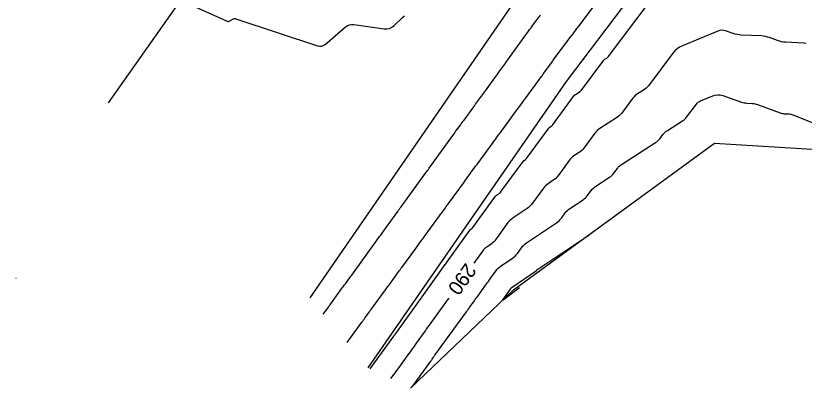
# Model space of a CAD drawing. Extents: x 1574966 to 1597594, y 720505 to 737840.
# Drawn here: x 1577544.3 to 1577874.4, y 724072.7 to 724228.5 of the extents above; entities that cross this region are included whole.
import ezdxf

# ---------------------------------------------------------------- set-up
doc = ezdxf.new("R2010")
doc.units = 0
for name, color, linetype in [('R_Contour Annot', 7, 'Continuous'), ('R_Contours', 7, 'Continuous'), ('S_BREAKLINE', 7, 'Continuous'), ('S_GRD_PT_SYM', 7, 'Continuous')]:
    doc.layers.add(name, color=color, linetype=linetype)

msp = doc.modelspace()

# ---------------------------------------------------------------- linework, layer by layer
at = {"layer": 'R_Contours'}
for points in [[(1577615.4, 724234.05), (1577632.74, 724226.3), (1577633.06, 724226.19), (1577633.37, 724226.17), (1577633.68, 724226.24), (1577633.98, 724226.39), (1577635.18, 724227.15), (1577635.49, 724227.3), (1577635.8, 724227.38), (1577636.13, 724227.38), (1577636.46, 724227.3), (1577670.63, 724215.95), (1577671.48, 724215.77), (1577672.28, 724215.81), (1577673.04, 724216.07), (1577673.76, 724216.56), (1577682.38, 724223.9), (1577683.15, 724224.43), (1577683.98, 724224.78), (1577684.86, 724224.93), (1577685.8, 724224.89), (1577698.58, 724223.1), (1577699.73, 724223.06), (1577700.8, 724223.28), (1577701.79, 724223.74), (1577702.69, 724224.46), (1577706.19, 724227.88), (1577707.07, 724228.59)], [(1577682.97, 724091.79), (1577689.18, 724100.24), (1577689.53, 724100.73), (1577689.89, 724101.22), (1577690.24, 724101.7), (1577690.59, 724102.19), (1577692, 724104.14), (1577692.35, 724104.63), (1577692.71, 724105.12), (1577693.06, 724105.61), (1577693.42, 724106.09), (1577699.09, 724113.81), (1577699.43, 724114.28), (1577699.78, 724114.75), (1577700.12, 724115.22), (1577700.46, 724115.7), (1577704.52, 724121.33), (1577704.86, 724121.79), (1577705.2, 724122.26), (1577705.54, 724122.72), (1577705.88, 724123.19), (1577711.72, 724131.14), (1577712.05, 724131.59), (1577712.38, 724132.04), (1577712.7, 724132.49), (1577713.03, 724132.94), (1577714.33, 724134.74), (1577714.66, 724135.19), (1577714.98, 724135.64), (1577715.31, 724136.09), (1577715.64, 724136.53), (1577721.68, 724144.75), (1577722, 724145.19), (1577722.31, 724145.62), (1577722.63, 724146.05), (1577722.94, 724146.49), (1577724.2, 724148.23), (1577724.51, 724148.67), (1577724.83, 724149.1), (1577725.15, 724149.53), (1577725.46, 724149.97), (1577731.71, 724158.46), (1577732.01, 724158.87), (1577732.32, 724159.29), (1577732.62, 724159.71), (1577732.92, 724160.13), (1577736.53, 724165.13), (1577736.83, 724165.54), (1577737.13, 724165.95), (1577737.43, 724166.36), (1577737.73, 724166.77), (1577744.14, 724175.49), (1577744.43, 724175.89), (1577744.72, 724176.28), (1577745.01, 724176.68), (1577745.3, 724177.08), (1577746.45, 724178.67), (1577746.73, 724179.06), (1577747.02, 724179.46), (1577747.31, 724179.86), (1577747.6, 724180.25), (1577754.22, 724189.25), (1577754.5, 724189.63), (1577754.77, 724190.01), (1577755.05, 724190.39), (1577755.33, 724190.77), (1577756.43, 724192.29), (1577756.7, 724192.68), (1577756.98, 724193.06), (1577757.26, 724193.44), (1577757.54, 724193.82), (1577764.36, 724203.09), (1577764.63, 724203.45), (1577764.89, 724203.82), (1577765.16, 724204.18), (1577765.42, 724204.55), (1577768.56, 724208.9), (1577768.83, 724209.26), (1577769.09, 724209.61), (1577769.35, 724209.97), (1577769.62, 724210.32), (1577776.86, 724219.95), (1577777.13, 724220.3), (1577777.39, 724220.66), (1577777.65, 724221.01), (1577777.91, 724221.37), (1577778.95, 724222.8), (1577779.21, 724223.16), (1577779.47, 724223.52), (1577779.73, 724223.87), (1577779.99, 724224.23), (1577787.26, 724233.88)], [(1577692.73, 724080.76), (1577702.55, 724094.42), (1577702.62, 724094.52), (1577702.69, 724094.62), (1577702.76, 724094.72), (1577702.83, 724094.81), (1577703.12, 724095.21), (1577703.19, 724095.3), (1577703.26, 724095.4), (1577703.33, 724095.5), (1577703.4, 724095.6), (1577712.98, 724108.93), (1577713.06, 724109.04), (1577713.13, 724109.14), (1577713.21, 724109.25), (1577713.29, 724109.36), (1577714.14, 724110.53), (1577714.2, 724110.62), (1577714.26, 724110.7), (1577714.33, 724110.79), (1577714.39, 724110.88), (1577724.11, 724124.4), (1577724.17, 724124.49), (1577724.24, 724124.59), (1577724.31, 724124.68), (1577724.38, 724124.78), (1577724.66, 724125.16), (1577724.73, 724125.26), (1577724.8, 724125.35), (1577724.87, 724125.45), (1577724.93, 724125.55), (1577734.58, 724138.96), (1577734.65, 724139.05), (1577734.73, 724139.14), (1577734.82, 724139.22), (1577734.91, 724139.28), (1577735.3, 724139.55), (1577735.39, 724139.62), (1577735.48, 724139.69), (1577735.55, 724139.78), (1577735.63, 724139.87), (1577745.15, 724153.04), (1577745.23, 724153.15), (1577745.32, 724153.24), (1577745.42, 724153.33), (1577745.52, 724153.41), (1577746.87, 724154.31), (1577746.98, 724154.39), (1577747.08, 724154.48), (1577747.18, 724154.57), (1577747.26, 724154.68), (1577756.71, 724167.62), (1577756.81, 724167.74), (1577756.91, 724167.85), (1577757.02, 724167.95), (1577757.15, 724168.04), (1577757.66, 724168.38), (1577757.78, 724168.47), (1577757.9, 724168.56), (1577758, 724168.67), (1577758.1, 724168.79), (1577767.4, 724181.46), (1577767.5, 724181.59), (1577767.62, 724181.71), (1577767.75, 724181.82), (1577767.89, 724181.92), (1577768.46, 724182.29), (1577768.59, 724182.39), (1577768.72, 724182.5), (1577768.84, 724182.62), (1577768.95, 724182.75), (1577778.09, 724195.14), (1577778.21, 724195.29), (1577778.34, 724195.42), (1577778.48, 724195.54), (1577778.63, 724195.64), (1577780.55, 724196.87), (1577780.7, 724196.98), (1577780.85, 724197.1), (1577780.98, 724197.24), (1577781.1, 724197.38), (1577790.55, 724209.95), (1577790.68, 724210.1), (1577790.81, 724210.23), (1577790.96, 724210.35), (1577791.11, 724210.46), (1577791.77, 724210.87), (1577791.93, 724210.98), (1577792.07, 724211.11), (1577792.21, 724211.24), (1577792.33, 724211.39), (1577809.43, 724234.13)], [(1577673.05, 724103.65), (1577674.94, 724106.22), (1577675.26, 724106.65), (1577675.57, 724107.08), (1577675.88, 724107.51), (1577676.19, 724107.94), (1577681.01, 724114.62), (1577681.34, 724115.07), (1577681.66, 724115.52), (1577681.99, 724115.97), (1577682.32, 724116.42), (1577683.64, 724118.21), (1577683.97, 724118.66), (1577684.29, 724119.11), (1577684.62, 724119.56), (1577684.95, 724120.01), (1577695.58, 724134.75), (1577695.92, 724135.23), (1577696.27, 724135.7), (1577696.61, 724136.18), (1577696.96, 724136.65), (1577698.35, 724138.54), (1577698.7, 724139.02), (1577699.04, 724139.49), (1577699.39, 724139.97), (1577699.73, 724140.44), (1577704.21, 724146.64), (1577704.57, 724147.14), (1577704.93, 724147.63), (1577705.29, 724148.13), (1577705.65, 724148.62), (1577707.1, 724150.59), (1577707.46, 724151.08), (1577707.82, 724151.58), (1577708.18, 724152.07), (1577708.53, 724152.56), (1577712.89, 724158.6), (1577713.27, 724159.12), (1577713.64, 724159.63), (1577714.01, 724160.15), (1577714.39, 724160.66), (1577715.89, 724162.71), (1577716.27, 724163.22), (1577716.64, 724163.73), (1577717.02, 724164.24), (1577717.39, 724164.76), (1577727.29, 724178.47), (1577727.68, 724179.01), (1577728.07, 724179.55), (1577728.46, 724180.09), (1577728.85, 724180.62), (1577730.43, 724182.77), (1577730.83, 724183.31), (1577731.22, 724183.84), (1577731.61, 724184.38), (1577732, 724184.92), (1577736.01, 724190.48), (1577736.42, 724191.04), (1577736.83, 724191.6), (1577737.23, 724192.16), (1577737.64, 724192.71), (1577739.28, 724194.94), (1577739.69, 724195.5), (1577740.1, 724196.05), (1577740.5, 724196.61), (1577740.91, 724197.17), (1577744.8, 724202.56), (1577745.22, 724203.14), (1577745.64, 724203.72), (1577746.06, 724204.3), (1577746.48, 724204.88), (1577748.18, 724207.18), (1577748.61, 724207.76), (1577749.03, 724208.34), (1577749.45, 724208.92), (1577749.87, 724209.5), (1577759, 724222.13), (1577759.44, 724222.75), (1577759.89, 724223.36), (1577760.35, 724223.98), (1577760.8, 724224.59), (1577762.64, 724227.02), (1577763.1, 724227.63), (1577763.55, 724228.25), (1577764, 724228.86)], [(1577875.2, 724217), (1577874.29, 724217.08), (1577866.56, 724217.46), (1577865.69, 724217.53), (1577864.83, 724217.67), (1577863.98, 724217.88), (1577863.15, 724218.16), (1577859.84, 724219.39), (1577859.01, 724219.66), (1577858.16, 724219.87), (1577857.3, 724220.01), (1577856.43, 724220.09), (1577847.93, 724220.49), (1577847.09, 724220.56), (1577846.26, 724220.69), (1577845.44, 724220.88), (1577844.63, 724221.13), (1577841.41, 724222.24), (1577840.61, 724222.45), (1577839.82, 724222.5), (1577839.03, 724222.4), (1577838.24, 724222.15), (1577823.36, 724215.96), (1577822.2, 724215.39), (1577821.14, 724214.68), (1577820.19, 724213.83), (1577819.35, 724212.85), (1577809.13, 724199.27), (1577808.68, 724198.72), (1577808.19, 724198.22), (1577807.65, 724197.77), (1577807.06, 724197.36), (1577804.64, 724195.84), (1577804.05, 724195.44), (1577803.51, 724194.98), (1577803.02, 724194.48), (1577802.56, 724193.93), (1577797.89, 724187.71), (1577797.44, 724187.17), (1577796.95, 724186.67), (1577796.41, 724186.22), (1577795.84, 724185.82), (1577788.77, 724181.3), (1577788.21, 724180.91), (1577787.69, 724180.47), (1577787.22, 724179.98), (1577786.79, 724179.45), (1577782.12, 724173.13), (1577781.7, 724172.62), (1577781.24, 724172.14), (1577780.74, 724171.71), (1577780.2, 724171.32), (1577777.94, 724169.86), (1577777.4, 724169.47), (1577776.89, 724169.04), (1577776.43, 724168.56), (1577776.01, 724168.04), (1577771.18, 724161.46), (1577770.77, 724160.95), (1577770.33, 724160.48), (1577769.84, 724160.06), (1577769.31, 724159.68), (1577767.12, 724158.24), (1577766.59, 724157.85), (1577766.1, 724157.43), (1577765.66, 724156.96), (1577765.25, 724156.46), (1577760.25, 724149.61), (1577759.85, 724149.11), (1577759.42, 724148.66), (1577758.94, 724148.24), (1577758.43, 724147.86), (1577752.14, 724143.66), (1577751.64, 724143.3), (1577751.18, 724142.89), (1577750.76, 724142.45), (1577750.37, 724141.96), (1577745.17, 724134.76), (1577744.8, 724134.29), (1577744.39, 724133.86), (1577743.94, 724133.46), (1577743.46, 724133.1), (1577741.45, 724131.74), (1577740.97, 724131.38), (1577740.53, 724130.99), (1577740.12, 724130.55), (1577739.74, 724130.08), (1577736.09, 724125)], [(1577710.39, 724073.44), (1577718.04, 724084), (1577718.19, 724084.21), (1577718.34, 724084.41), (1577718.48, 724084.61), (1577718.63, 724084.81), (1577719.21, 724085.63), (1577719.36, 724085.83), (1577719.5, 724086.03), (1577719.65, 724086.23), (1577719.8, 724086.44), (1577732.95, 724104.61), (1577733.32, 724105.12), (1577733.69, 724105.64), (1577734.06, 724106.16), (1577734.43, 724106.67), (1577735.92, 724108.74), (1577736.29, 724109.26), (1577736.66, 724109.77), (1577737.04, 724110.29), (1577737.41, 724110.8), (1577741.69, 724116.72), (1577742.14, 724117.35), (1577742.59, 724117.97), (1577743.04, 724118.6), (1577743.49, 724119.22), (1577745.29, 724121.72), (1577745.76, 724122.32), (1577746.28, 724122.88), (1577746.85, 724123.38), (1577747.46, 724123.84), (1577752.21, 724127.06), (1577752.8, 724127.5), (1577753.35, 724127.98), (1577753.85, 724128.51), (1577754.3, 724129.09), (1577756.04, 724131.48), (1577756.49, 724132.06), (1577756.99, 724132.59), (1577757.54, 724133.07), (1577758.13, 724133.5), (1577770.74, 724141.92), (1577771.29, 724142.33), (1577771.81, 724142.78), (1577772.28, 724143.27), (1577772.71, 724143.81), (1577774.34, 724146.04), (1577774.77, 724146.58), (1577775.24, 724147.07), (1577775.75, 724147.52), (1577776.31, 724147.92), (1577781.79, 724151.53), (1577782.32, 724151.91), (1577782.81, 724152.34), (1577783.27, 724152.81), (1577783.68, 724153.32), (1577785.24, 724155.45), (1577785.65, 724155.96), (1577786.1, 724156.43), (1577786.59, 724156.85), (1577787.13, 724157.23), (1577792.85, 724160.94), (1577793.36, 724161.31), (1577793.83, 724161.71), (1577794.26, 724162.15), (1577794.65, 724162.64), (1577796.15, 724164.66), (1577796.54, 724165.15), (1577796.97, 724165.59), (1577797.44, 724165.99), (1577797.95, 724166.35), (1577812.19, 724175.44), (1577812.67, 724175.78), (1577813.12, 724176.16), (1577813.54, 724176.58), (1577813.91, 724177.04), (1577815.35, 724178.95), (1577815.72, 724179.4), (1577816.14, 724179.82), (1577816.59, 724180.2), (1577817.08, 724180.54), (1577823.48, 724184.56), (1577823.95, 724184.89), (1577824.38, 724185.25), (1577824.78, 724185.65), (1577825.14, 724186.09), (1577829.26, 724191.57), (1577829.63, 724192), (1577830.04, 724192.37), (1577830.5, 724192.67), (1577831.01, 724192.92), (1577836.1, 724195.04), (1577837.13, 724195.37), (1577838.17, 724195.5), (1577839.21, 724195.43), (1577840.25, 724195.17), (1577848.14, 724192.42), (1577848.68, 724192.25), (1577849.24, 724192.13), (1577849.8, 724192.04), (1577850.36, 724191.99), (1577852.65, 724191.88), (1577853.22, 724191.84), (1577853.78, 724191.74), (1577854.33, 724191.61), (1577854.87, 724191.43), (1577864.26, 724187.94), (1577864.69, 724187.79), (1577865.13, 724187.69), (1577865.57, 724187.61), (1577866.02, 724187.57), (1577867.84, 724187.49), (1577868.29, 724187.45), (1577868.73, 724187.37), (1577869.16, 724187.26), (1577869.59, 724187.1), (1577879.12, 724183.29)], [(1577755.21, 724114.69), (1577748.91, 724109.89), (1577748.39, 724109.53), (1577748.16, 724109.47), (1577748.22, 724109.7), (1577748.56, 724110.23), (1577751.38, 724114.13), (1577751.43, 724114.2), (1577751.49, 724114.28), (1577751.54, 724114.35), (1577751.6, 724114.43), (1577751.82, 724114.73), (1577751.87, 724114.81), (1577751.94, 724114.87), (1577752, 724114.93), (1577752.08, 724114.99), (1577762.31, 724121.92), (1577762.36, 724121.96), (1577762.41, 724122), (1577762.45, 724122.04), (1577762.49, 724122.09), (1577762.63, 724122.29), (1577762.67, 724122.34), (1577762.71, 724122.39), (1577762.76, 724122.43), (1577762.81, 724122.46), (1577784.15, 724136.72)], [(1577725.57, 724110.39), (1577724.83, 724109.36), (1577724.4, 724108.76), (1577723.98, 724108.17), (1577723.55, 724107.58), (1577723.12, 724106.99), (1577717.38, 724099.05), (1577716.85, 724098.32), (1577716.32, 724097.59), (1577715.79, 724096.85), (1577715.26, 724096.12), (1577711.95, 724091.51), (1577711.37, 724090.71), (1577710.8, 724089.91), (1577710.22, 724089.11), (1577709.64, 724088.31), (1577707.33, 724085.11), (1577706.75, 724084.31), (1577706.17, 724083.51), (1577705.59, 724082.71), (1577705.02, 724081.91), (1577701.24, 724076.66)]]:
    msp.add_lwpolyline(points, dxfattribs=at)
at = {"layer": 'S_BREAKLINE'}
for p, q in [((1577672.47, 724319.11), (1577582.95, 724192.15)), ((1577791.37, 724290.51), (1577667.37, 724110.44)), ((1577774.86, 724200.98), (1577819.84, 724260.57)), ((1577691.83, 724081.2), (1577774.86, 724200.98)), ((1577752.72, 724113.77), (1577836.88, 724175.22)), ((1577836.88, 724175.22), (1577950.4, 724168.3)), ((1577709.57, 724072.66), (1577752.72, 724113.77))]:
    msp.add_line(p, q, dxfattribs=at)
at = {"layer": 'S_GRD_PT_SYM'}
msp.add_lwpolyline([(1577544.35, 724118.73), (1577544.35, 724118.78), (1577544.35, 724118.73), (1577544.3, 724118.73), (1577544.35, 724118.73), (1577544.35, 724118.68), (1577544.35, 724118.73), (1577544.4, 724118.73)], dxfattribs=at)
msp.add_lwpolyline([(1577544.35, 724118.73), (1577544.35, 724118.78), (1577544.35, 724118.73), (1577544.3, 724118.73), (1577544.35, 724118.73), (1577544.35, 724118.68), (1577544.35, 724118.73), (1577544.4, 724118.73)], dxfattribs=at)
msp.add_lwpolyline([(1577544.35, 724118.73), (1577544.35, 724118.78), (1577544.35, 724118.73), (1577544.3, 724118.73), (1577544.35, 724118.73), (1577544.35, 724118.68), (1577544.35, 724118.73), (1577544.4, 724118.73)], dxfattribs=at)

# ---------------------------------------------------------------- texts
at = {"layer": 'R_Contour Annot'}
msp.add_text('290', height=6, rotation=234.2424, dxfattribs=at).set_placement((1577732.69, 724125.41))

doc.saveas('drawing.dxf')
